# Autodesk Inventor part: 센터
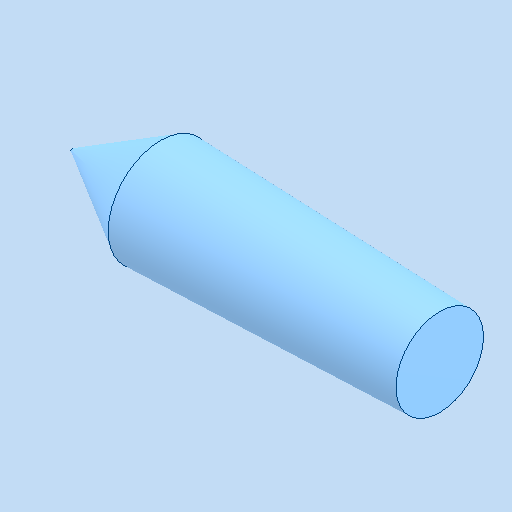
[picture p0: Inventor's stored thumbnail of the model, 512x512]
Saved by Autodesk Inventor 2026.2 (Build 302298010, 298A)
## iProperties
Created: 2026-08
Part Number: 센터
Material: 스테인리스강
Document SubType Name: Modeling
Designer: PC-2-06
Density: 8.08 g/cm^3
Appearance: 기본값
Author: jhkim
Sending System: Autodesk Inventor 2027
Preprocessor: ST-DEVELOPER v20.1
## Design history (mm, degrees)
feature "솔리드1"
node "솔리드2"
